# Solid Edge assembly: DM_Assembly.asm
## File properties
Author: hhakima
Template: Normal.asm
Last saved by: Houman
Revision: 13
Application: Solid Edge
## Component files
Part - Lens Holder (Top).par
Part - DM.par
Part - Lens Holder (Bottom).par
Screw_M2.5_6mm.par
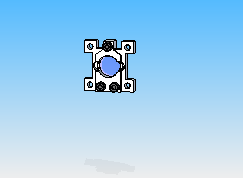
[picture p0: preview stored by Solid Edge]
